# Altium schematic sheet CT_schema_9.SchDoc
size 382 x 278 mm
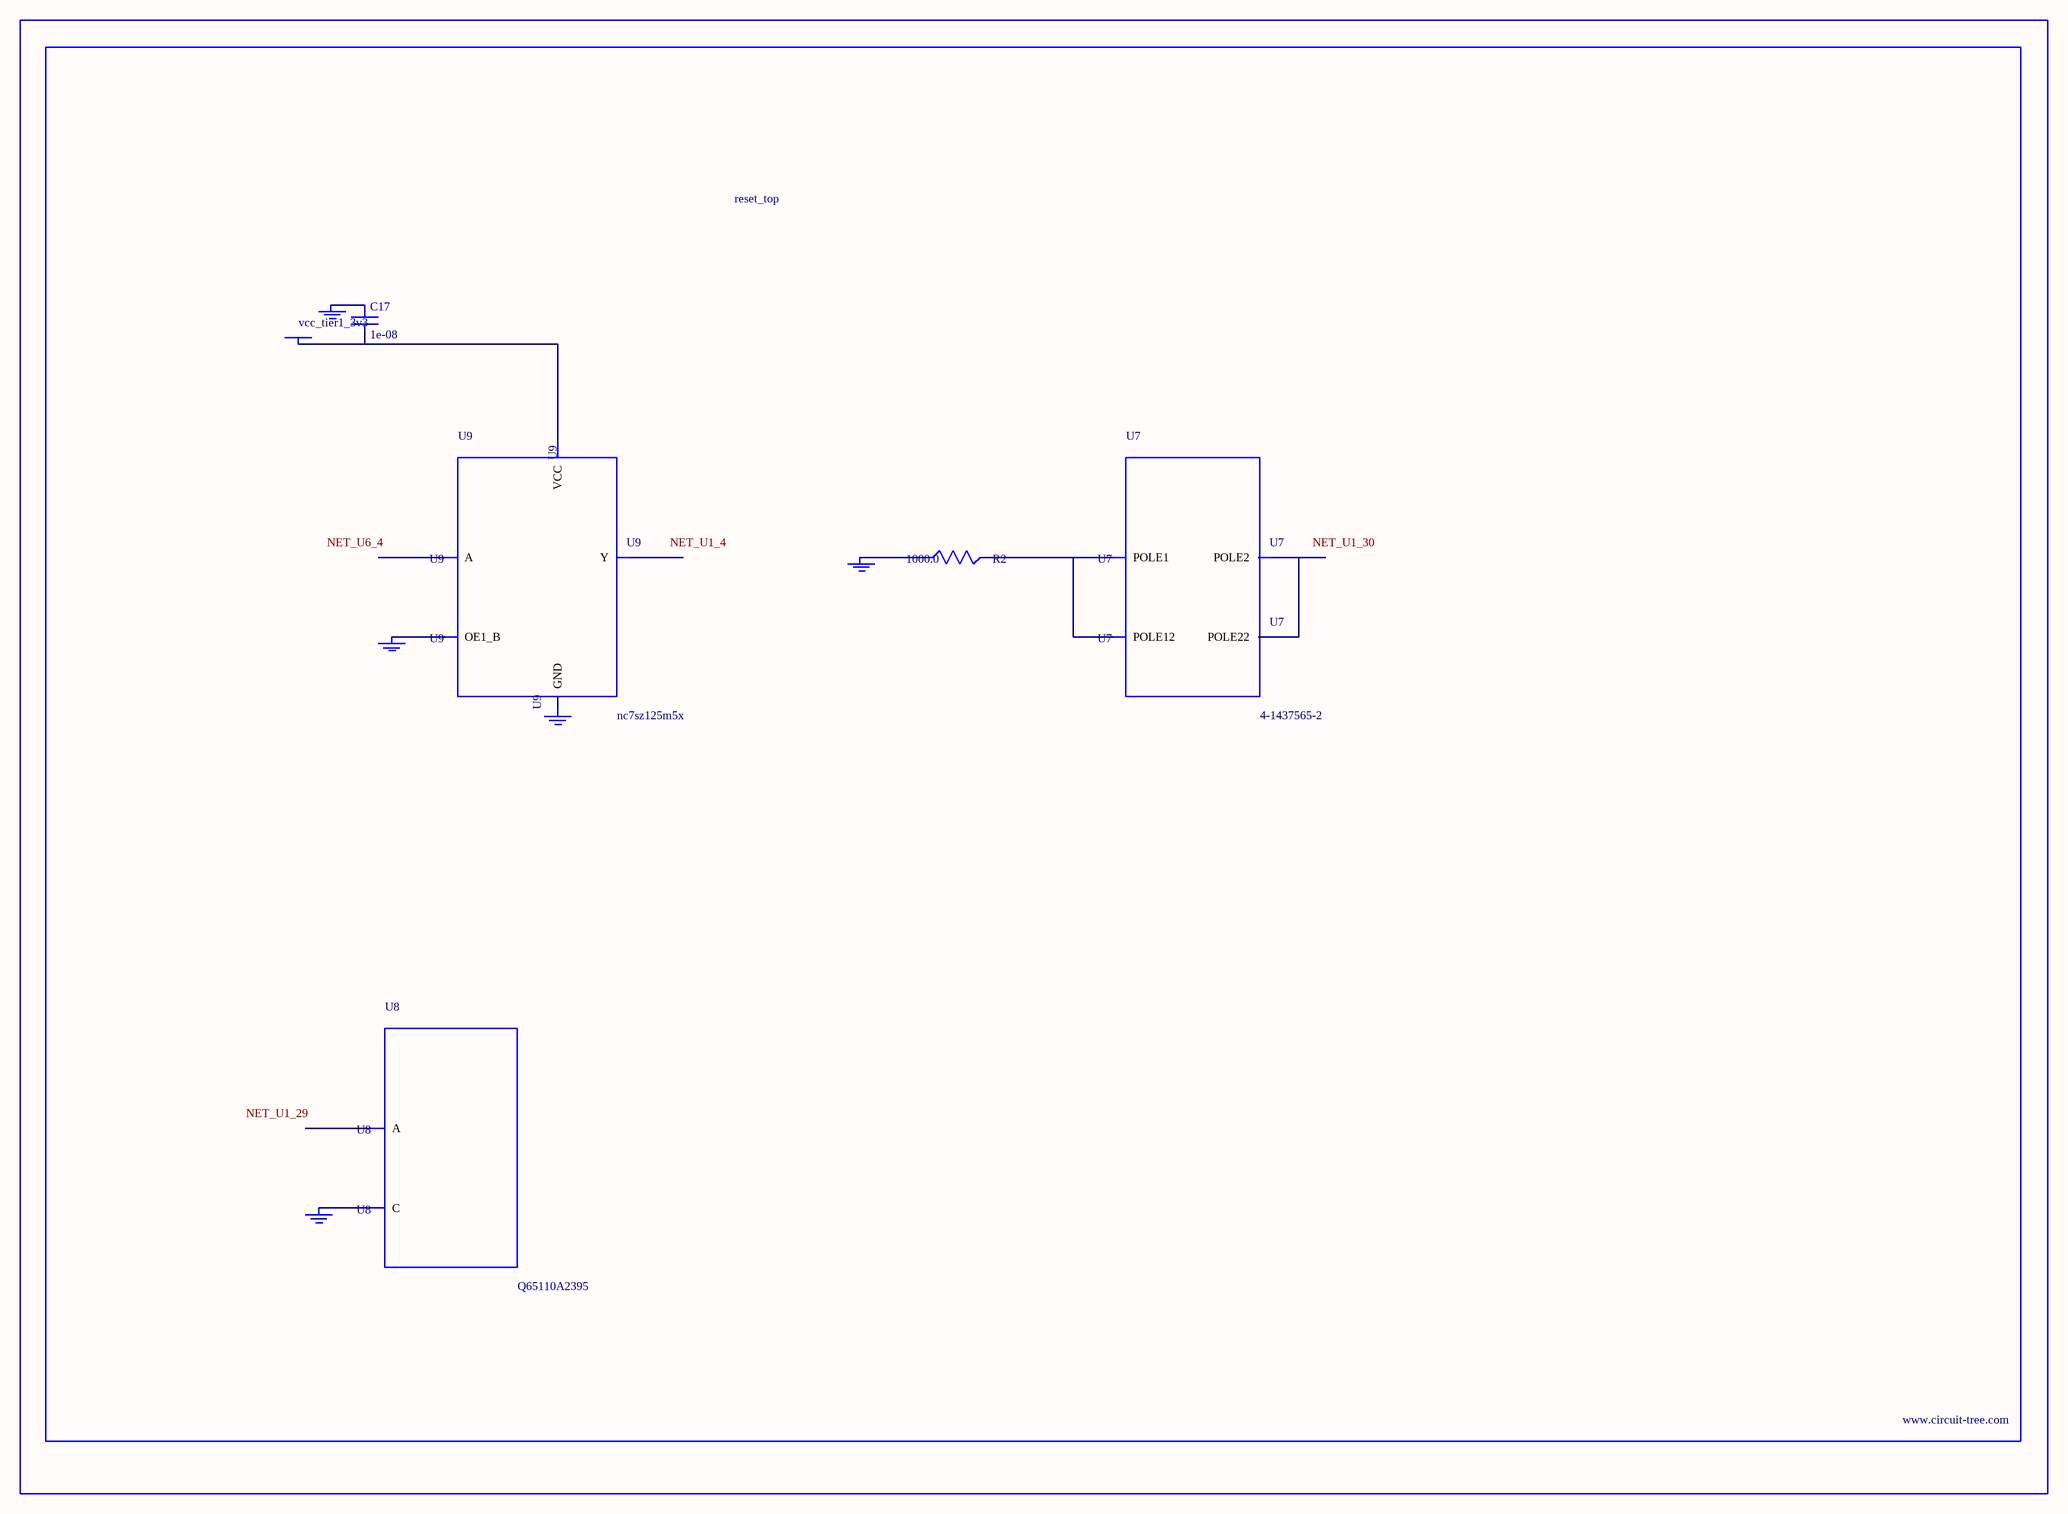
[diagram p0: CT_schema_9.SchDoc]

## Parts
BORDER8  (no value)
C17  1e-08  [C0402]
GND_INSTANCE_8_0  (no value)
GND_INSTANCE_8_1  (no value)
GND_INSTANCE_8_2  (no value)
GND_INSTANCE_8_3  (no value)
GND_INSTANCE_8_4  (no value)
POWER_INSTANCE_8_0  vcc_tier1_3v3
R2  1000.0  [R0603]
U7  4-1437565-2  [SW_4-1437565-2]
U8  Q65110A2395  [LGM67K-G1J2-24-Z]
U9  nc7sz125m5x  [NC7SZ125M5X]

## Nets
NetC17_1: C17.1 GND_INSTANCE_8_2.0(GND)
NetC17_2: C17.2 POWER_INSTANCE_8_0.0(PWR) U9.5(VCC)
NetGND_INSTANCE_8_0_0: GND_INSTANCE_8_0.0(GND) R2.1
NetGND_INSTANCE_8_1_0: GND_INSTANCE_8_1.0(GND) U8.C
NetGND_INSTANCE_8_3_0: GND_INSTANCE_8_3.0(GND) U9.1(OE1_B)
NetGND_INSTANCE_8_4_0: GND_INSTANCE_8_4.0(GND) U9.3(GND)
NetR2_2: R2.2 U7.1(POLE1) U7.2(POLE12)
NetU7_3: U7.3(POLE2) U7.4(POLE22)

Not connected (* = marked no-connect by the designer): U8 A; U9 2(A) 4(Y)

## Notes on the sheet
- Labels drawn without touching a wire or pin: NET_U1_4, NET_U1_29, NET_U1_30, NET_U6_4

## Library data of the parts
BORDER8 = BORDER_PAGE8
C17 = C0402C103K3RAC
GND_INSTANCE_8_0-GND_INSTANCE_8_4 = GND
POWER_INSTANCE_8_0 = PWR
R2 = RC0603JR-071KL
